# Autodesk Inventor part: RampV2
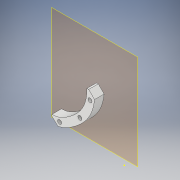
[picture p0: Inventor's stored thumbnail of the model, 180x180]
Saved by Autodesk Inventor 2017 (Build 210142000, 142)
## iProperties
Created: 2017-04
Part Number: RampV2
Material: ABS Plastic
Document SubType Name: Modeling
Designer: 1460374
Density: 1.06 g/cm^3
Appearance: Smooth - White
Author: 1460374
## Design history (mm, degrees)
workplane "Work Plane1"
sketch "Sketch1" dims "d0" = 7.62
  geometry: L1 (-117.357, 5.198)-(-117.357, 12.818); L2 (-60.667, 77.597)-(-53.047, 77.597); 4 further points
  constraints: 4 end point, 1 horizontal, 1 vertical, 8 other
extrude "Extrusion1" new body sketch "Sketch1" distance "d1" = 15.5; taper "d2" = 0 deg
chamfer "Chamfer1" distance "d3" = 4.7625; stored, may be unused: second distance "d4" = 3.175, angle "d5" = 45 deg
chamfer "Chamfer2" distance "d6" = 4.7625; stored, may be unused: second distance "d7" = 3.175, angle "d8" = 45 deg
sketch "Sketch2"
  geometry: 1 further point
thicken "Thicken1" dims "d9" = 2.54, "d10" = 2.54
sketch "Sketch4"
  geometry: C1 r 3.225 at (-104.916, 8.353); C2 r 3.225 at (-72.045, 30.571); C3 r 3.225 at (-55.67, 63.321); 1 further point
  constraints: 3 centre point
  dimensions: "d11" = 6.45 diameter of C1; "d12" = 6.45 diameter of C2; "d13" = 6.45 diameter of C3
thicken "Thicken2" dims "d14" = 2.54, "d15" = 2.54
extrude "Extrusion2" cut sketch "Sketch4" distance "d16" = 16.25001; taper "d17" = 0 deg
body "Solid1"
